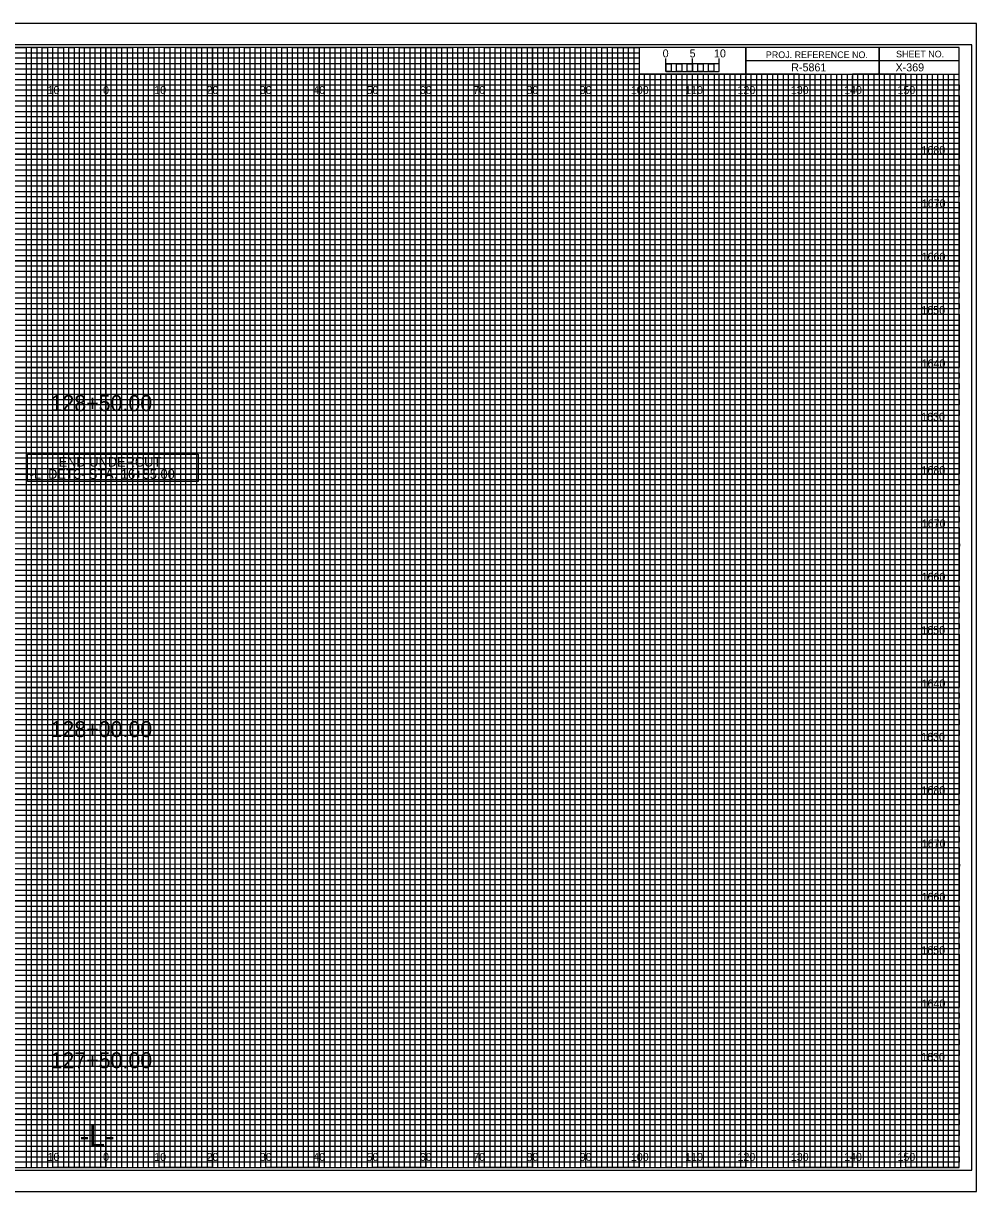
# Model space of a CAD drawing. Extents: x -13 to 323, y -5 to 2414.
# Drawn here: x 144.5 to 323.3, y 1095.5 to 1314.5 of the extents above; entities that cross this region are included whole.
import ezdxf

# ---------------------------------------------------------------- set-up
doc = ezdxf.new("R2010")
doc.units = 0
for name, color, linetype in [('Exist XS Center Line Elevation Label', 7, 'Continuous'), ('Prop Grid Mask', 7, 'Continuous'), ('Prop XS Alignment Label', 7, 'Continuous'), ('Prop XS Bar Scale Labels', 7, 'Continuous'), ('Prop XS Elevation Labels', 7, 'Continuous'), ('Prop XS Offset Labels', 7, 'Continuous'), ('Prop XS Project Number', 7, 'Continuous'), ('Prop XS Sheet Number', 7, 'Continuous'), ('Prop XS Station Labels', 7, 'Continuous'), ('Sheet Cross Section CELL', 7, 'Continuous'), ('Sheet Cross Section Grid Major CELL', 7, 'Continuous'), ('Sheet Cross Section Grid Middle CELL', 7, 'Continuous'), ('Sheet Cross Section Grid Minor 1 CELL', 7, 'Continuous'), ('Sheet Cross Section Grid Minor 2 CELL', 7, 'Continuous'), ('Sheet Cross Section Scale CELL', 7, 'Continuous'), ('Sheet Cutting Line CELL', 7, 'Continuous'), ('Sheet DOT Grid CELL', 7, 'Continuous'), ('Sheet Plot Border Inside CELL', 7, 'Continuous'), ('Sheet Plot Border Outside CELL', 7, 'Continuous')]:
    doc.layers.add(name, color=color, linetype=linetype)

msp = doc.modelspace()

# ---------------------------------------------------------------- linework, layer by layer
at = {"layer": 'Prop Grid Mask'}
msp.add_lwpolyline([(145.3, 1233.73), (177.29, 1233.73), (177.29, 1228.6), (145.3, 1228.6)], close=True, dxfattribs=at)
at = {"layer": 'Sheet Cross Section CELL'}
for p, q in [((305, 1310), (305, 1305)), ((305, 1305), (305, 1310)), ((280, 1307.5), (280, 1305)), ((320, 1307.49), (280, 1307.49)), ((280, 1305), (320, 1305))]:
    msp.add_line(p, q, dxfattribs=at)
for points in [[(320, 1310), (0, 1310), (0, 1100), (320, 1100)], [(280, 1310), (260, 1310), (260, 1305.03), (280, 1305.03)], [(320, 1310), (280, 1310), (280, 1305), (320, 1305)]]:
    msp.add_lwpolyline(points, close=True, dxfattribs=at)
at = {"layer": 'Sheet Cross Section Grid Major CELL'}
for p, q in [((150, 1310), (140, 1310)), ((150, 1100), (150, 1310)), ((170, 1310), (160, 1310)), ((160, 1310), (160, 1100)), ((170, 1100), (170, 1310)), ((190, 1310), (180, 1310)), ((180, 1310), (180, 1100)), ((190, 1100), (190, 1310)), ((210, 1310), (200, 1310)), ((200, 1310), (200, 1100)), ((210, 1100), (210, 1310)), ((230, 1310), (220, 1310)), ((220, 1310), (220, 1100)), ((230, 1100), (230, 1310)), ((250, 1310), (240, 1310)), ((240, 1310), (240, 1100)), ((250, 1100), (250, 1310)), ((260, 1310), (260, 1100)), ((270, 1100), (270, 1305)), ((290, 1305), (280, 1305)), ((280, 1305), (280, 1100)), ((290, 1100), (290, 1305)), ((310, 1305), (300, 1305)), ((300, 1305), (300, 1100)), ((310, 1100), (310, 1305)), ((160, 1100), (150, 1100)), ((180, 1100), (170, 1100)), ((200, 1100), (190, 1100)), ((220, 1100), (210, 1100)), ((240, 1100), (230, 1100)), ((260, 1100), (250, 1100)), ((280, 1100), (270, 1100)), ((300, 1100), (290, 1100)), ((320, 1100), (310, 1100)), ((320, 1100), (320, 1100))]:
    msp.add_line(p, q, dxfattribs=at)
for points in [[(0, 1300), (320, 1300), (320, 1290), (0, 1290)], [(0, 1280), (320, 1280), (320, 1270), (0, 1270)], [(0, 1260), (320, 1260), (320, 1250), (0, 1250)], [(0, 1240), (320, 1240), (320, 1230), (0, 1230)], [(0, 1220), (320, 1220), (320, 1210), (0, 1210)], [(0, 1200), (320, 1200), (320, 1190), (0, 1190)], [(0, 1180), (320, 1180), (320, 1170), (0, 1170)], [(0, 1160), (320, 1160), (320, 1150), (0, 1150)], [(0, 1140), (320, 1140), (320, 1130), (0, 1130)], [(0, 1120), (320, 1120), (320, 1110), (0, 1110)]]:
    msp.add_lwpolyline(points, dxfattribs=at)
at = {"layer": 'Sheet Cross Section Grid Middle CELL'}
for points in [[(135, 1310), (145, 1310), (145, 1100), (155, 1100), (155, 1310), (165, 1310), (165, 1100), (175, 1100), (175, 1310), (185, 1310), (185, 1100), (195, 1100), (195, 1310), (205, 1310), (205, 1100), (215, 1100), (215, 1310), (225, 1310), (225, 1100), (235, 1100), (235, 1310), (245, 1310), (245, 1100), (255, 1100), (255, 1310), (259.93, 1310), (260, 1310), (260, 1305), (264.99, 1305), (264.99, 1100), (275, 1100), (275, 1305), (285, 1305), (285, 1100), (295, 1100), (295, 1305), (305, 1305), (305, 1100), (315, 1100), (315, 1305)], [(0, 1305), (275, 1305)], [(0, 1285), (320, 1285), (320, 1295), (0, 1295)], [(0, 1265), (320, 1265), (320, 1275), (0, 1275)], [(0, 1245), (320, 1245), (320, 1255), (0, 1255)], [(0, 1225), (320, 1225), (320, 1235), (0, 1235)], [(0, 1205), (320, 1205), (320, 1215), (0, 1215)], [(0, 1185), (320, 1185), (320, 1195), (0, 1195)], [(0, 1165), (320, 1165), (320, 1175), (0, 1175)], [(0, 1145), (320, 1145), (320, 1155), (0, 1155)], [(0, 1125), (320, 1125), (320, 1135), (0, 1135)], [(0, 1105), (320, 1105), (320, 1115), (0, 1115)]]:
    msp.add_lwpolyline(points, dxfattribs=at)
at = {"layer": 'Sheet Cross Section Grid Minor 1 CELL'}
for p, q in [((0, 1309), (260, 1309)), ((260, 1307.98), (0, 1307.98)), ((260, 1309), (260, 1307.98)), ((0, 1307), (260, 1307)), ((260, 1305.89), (0, 1305.89)), ((260, 1307), (260, 1305.89)), ((0, 1304), (320, 1304))]:
    msp.add_line(p, q, dxfattribs=at)
for points in [[(0, 1303), (270, 1303), (320, 1303), (320, 1302), (0, 1302)], [(0, 1301), (320, 1301), (320, 1299), (0, 1299)], [(0, 1298), (320, 1298), (320, 1297), (0, 1296.98)], [(0, 1296), (320, 1296), (320, 1294), (0, 1294)], [(0, 1293), (320, 1293), (320, 1292), (0, 1292)], [(0, 1291), (320, 1291), (320, 1289), (0, 1289)], [(0, 1288), (320, 1288), (320, 1287), (0, 1287)], [(0, 1286), (320, 1286), (320, 1284), (0, 1284)], [(0, 1283), (320, 1283), (320, 1282), (0, 1282)], [(0, 1281), (320, 1281), (320, 1279), (0, 1279)], [(0, 1278), (320, 1278), (320, 1277), (0, 1277)], [(0, 1276), (320, 1276), (320, 1273.95), (320, 1273), (320, 1272), (0, 1272)], [(0, 1274), (320, 1274), (320, 1273), (0, 1273)], [(0, 1271), (320, 1271), (320, 1269), (0, 1269.03)], [(0, 1269.03), (320, 1269), (320, 1268), (0, 1268)], [(0, 1267), (320, 1267), (320, 1266), (0, 1266)], [(0, 1264), (320, 1264), (320, 1263), (0, 1263)], [(0, 1262), (320, 1262), (320, 1261), (0, 1261)], [(-0.07, 1258.89), (320, 1258.89), (320, 1257.88), (-0.07, 1257.88)], [(0, 1257), (320, 1257), (320, 1256), (0, 1256)], [(0, 1254), (320, 1254), (320, 1253), (0, 1253)], [(0, 1252), (320, 1252), (320, 1251), (0, 1251)], [(0, 1249), (320, 1249), (320, 1248), (0, 1248)], [(0, 1247), (320, 1247), (320, 1246), (0, 1246)], [(0, 1244), (320, 1244), (320, 1243), (0, 1243)], [(0, 1242), (320, 1242), (320, 1241), (0, 1241)], [(0, 1239), (320, 1239), (319.99, 1237.98), (0, 1238)], [(0, 1237), (320, 1237), (320, 1236), (0, 1236)], [(0, 1234), (320, 1234), (320, 1233), (0, 1233)], [(0, 1232), (320, 1232), (320, 1231), (0, 1231)], [(0, 1229), (320, 1229), (320, 1228), (0, 1228)], [(0, 1227), (320, 1227), (320, 1226), (0, 1226)], [(0, 1224), (320, 1224), (320, 1223), (0, 1223)], [(0, 1222), (320, 1222), (320, 1221), (0, 1221)], [(0, 1219), (320, 1219), (320, 1218), (0, 1218)], [(0, 1216.99), (320.07, 1216.91), (320, 1216), (0, 1216)], [(0, 1214), (320, 1214), (320, 1213), (0, 1213)], [(0, 1212), (320, 1212), (320, 1211), (0, 1211)], [(0, 1209), (320, 1209), (320, 1208), (0, 1208)], [(0, 1207), (320, 1207), (320, 1206), (0, 1206)], [(0, 1204), (320, 1204), (320, 1203), (0, 1203)], [(0, 1202), (320, 1202), (320, 1201), (0, 1201)], [(0, 1199), (320, 1199), (320, 1198), (0, 1198)], [(0, 1197), (320, 1197), (320, 1196), (0, 1196)], [(0, 1194), (320, 1194), (320, 1193), (0, 1193)], [(0, 1192), (320, 1192), (320, 1191), (0, 1191)], [(0, 1189), (320, 1189), (320, 1188), (0, 1188)], [(0, 1187), (320, 1187), (320, 1186), (0, 1186)], [(0, 1184), (320, 1184), (320, 1183), (0, 1183)], [(0, 1182), (320, 1182), (320, 1181), (0, 1181)], [(0, 1179), (320, 1179), (319.99, 1177.98), (0, 1178)], [(0, 1177), (320, 1177), (320, 1176), (0, 1176)], [(0, 1174), (320, 1174), (320, 1173), (0, 1173)], [(0, 1172), (320, 1172), (320, 1171), (0, 1171)], [(0, 1169), (320, 1169), (320, 1168), (0, 1168)], [(0, 1167), (320, 1167), (320, 1166), (0, 1166)], [(0, 1164), (320, 1164), (320, 1163), (0, 1163)], [(0, 1162), (320, 1162), (320, 1161), (0, 1161)], [(0, 1159), (320, 1159), (320, 1158), (0, 1158)], [(0, 1156.99), (320.07, 1156.91), (320, 1156), (0, 1156)], [(0, 1154), (320, 1154), (320, 1153), (0, 1153)], [(0, 1152), (320, 1152), (320, 1151), (0, 1151)], [(0, 1149), (320, 1149), (320, 1148), (0, 1148)], [(0, 1147), (320, 1147), (320, 1146), (0, 1146)], [(0, 1144), (320, 1144), (320, 1143), (0, 1143)], [(0, 1142), (320, 1142), (320, 1141), (0, 1141)], [(0, 1139), (320, 1139), (320, 1138), (0, 1138)], [(0, 1137), (320, 1137), (320, 1136), (0, 1136)], [(0, 1134), (320, 1134), (320, 1133), (0, 1133)], [(0, 1132), (320, 1132), (320, 1131), (0, 1131)], [(0, 1129), (320, 1129), (320, 1128), (0, 1128)], [(0, 1127), (320, 1127), (320, 1126), (0, 1126)], [(0, 1124), (320, 1124), (320, 1123), (0, 1123)], [(0, 1122), (320, 1122), (320, 1121), (0, 1121)], [(0, 1119), (320, 1119), (320, 1118), (0, 1118)], [(0, 1117), (320, 1117), (320, 1116), (0, 1116)], [(0, 1114), (320, 1114), (320, 1113), (0, 1113)], [(0, 1112), (320, 1112), (320, 1111), (0, 1111)], [(0, 1109), (320, 1109), (320, 1108), (0, 1108)], [(0, 1107), (320, 1107), (320, 1106), (0, 1106)], [(0, 1104), (320, 1104), (320, 1103), (0, 1103)], [(0, 1102), (320, 1102), (320, 1101), (0, 1101)]]:
    msp.add_lwpolyline(points, dxfattribs=at)
at = {"layer": 'Sheet Cross Section Grid Minor 2 CELL'}
for p, q in [((267, 1305), (266.01, 1305)), ((266.01, 1305), (266.01, 1100)), ((267, 1100), (267, 1305)), ((269, 1305), (268, 1305)), ((268, 1305), (268, 1100)), ((269, 1100), (269, 1305)), ((266.01, 1100), (265, 1100)), ((268, 1100), (267, 1100))]:
    msp.add_line(p, q, dxfattribs=at)
for points in [[(145, 1100), (146, 1100), (146, 1310), (147, 1310), (147, 1100)], [(147, 1100), (148, 1100), (148, 1310), (149, 1310), (149, 1100)], [(150, 1100), (151, 1100), (151, 1310), (152, 1310), (152, 1100)], [(152, 1100), (153, 1100), (153, 1310), (154, 1310), (154, 1100)], [(155, 1100), (156, 1100), (156, 1310), (157, 1310), (157, 1100)], [(157, 1100), (158, 1100), (158, 1310), (159, 1310), (159, 1100)], [(160, 1100), (161, 1100), (161, 1310), (162, 1310), (162, 1100)], [(162, 1100), (163, 1100), (163, 1310), (164, 1310), (164, 1100)], [(165, 1100), (166, 1100), (166, 1310), (167, 1310), (167, 1100)], [(167, 1100), (168, 1100), (168, 1310), (169, 1310), (169, 1100)], [(170, 1100), (171, 1100), (171, 1310), (172, 1310), (172, 1100)], [(172, 1100), (173, 1100), (173, 1310), (174, 1310), (174, 1100)], [(175, 1100), (176, 1100), (176, 1310), (177, 1310), (177, 1100)], [(177, 1100), (178, 1100), (178, 1310), (179, 1310), (179, 1100)], [(180, 1100), (181, 1100), (181, 1310), (182, 1310), (182, 1100)], [(182, 1100), (183, 1100), (183, 1310), (184, 1310), (184, 1100)], [(185, 1100), (186, 1100), (186, 1310), (187, 1310), (187, 1100)], [(187, 1100), (188, 1100), (188, 1310), (189, 1310), (189, 1100)], [(190, 1100), (191, 1100), (191, 1310), (192, 1310), (192, 1100)], [(192, 1100), (193, 1100), (193, 1310), (194, 1310), (194, 1100)], [(195, 1100), (196, 1100), (196, 1310), (197, 1310), (197, 1100)], [(197, 1100), (198, 1100), (198, 1310), (199, 1310), (199, 1100)], [(200, 1100), (201, 1100), (201, 1310), (202, 1310), (202, 1100)], [(202, 1100), (203, 1100), (203, 1310), (204, 1310), (204, 1100)], [(205, 1100), (206, 1100), (206, 1310), (207, 1310), (207, 1100)], [(207, 1100), (208, 1100), (208, 1310), (209, 1310), (209, 1100)], [(210, 1100), (211, 1100), (211, 1310), (212, 1310), (212, 1100)], [(212, 1100), (213, 1100), (213, 1310), (214, 1310), (214, 1100)], [(215, 1100), (216, 1100), (216, 1310), (217, 1310), (217, 1100)], [(217, 1100), (218, 1100), (218, 1310), (219, 1310), (219, 1100)], [(220, 1100), (221, 1100), (221, 1310), (222, 1310), (222, 1100)], [(222, 1100), (223, 1100), (223, 1310), (224, 1310), (224, 1100)], [(225, 1100), (226, 1100), (226, 1310), (227, 1310), (227, 1100)], [(227, 1100), (228, 1100), (228, 1310), (229, 1310), (229, 1100)], [(230, 1100), (231, 1100), (231, 1310), (232, 1310), (232, 1100)], [(232, 1100), (233, 1100), (233, 1310), (234, 1310), (234, 1100)], [(235, 1100), (236, 1100), (236, 1310), (237, 1310), (237, 1100)], [(237, 1100), (238, 1100), (238, 1310), (239, 1310), (239, 1100)], [(240, 1100), (241, 1100), (241, 1310), (242, 1310), (242, 1100)], [(242, 1100), (243, 1100), (243, 1310), (244, 1310), (244, 1100)], [(245, 1100), (246, 1100), (246, 1310), (247, 1310), (247, 1100)], [(247, 1100), (248, 1100), (248, 1310), (249, 1310), (249, 1100)], [(250, 1100), (251, 1100), (251, 1310), (252, 1310), (252, 1100)], [(252, 1100), (253, 1100), (253, 1310), (254, 1310), (254, 1100)], [(255, 1100), (256, 1100), (256, 1310), (257, 1310), (257, 1100)], [(257, 1100), (258, 1100), (258, 1310), (259, 1310), (259, 1100)], [(260, 1100), (261, 1100), (261, 1305), (262.02, 1305), (262.02, 1100)], [(262, 1100), (263, 1100), (263, 1305), (263.99, 1305), (263.99, 1100)], [(270, 1100), (270.98, 1100), (270.98, 1305), (272, 1305), (272, 1100)], [(272, 1100), (273, 1100), (273, 1305), (274.05, 1305), (274.05, 1100)], [(275, 1100), (276, 1100), (276, 1305), (277, 1305), (277, 1100)], [(277, 1100), (278, 1100), (278, 1305), (279, 1305), (279, 1100)], [(280, 1100), (281, 1100), (281, 1305), (282, 1305), (282, 1100)], [(282, 1100), (283, 1100), (283, 1305), (284, 1305), (284, 1100)], [(285, 1100), (286, 1100), (286, 1305), (287, 1305), (287, 1100)], [(287, 1100), (288, 1100), (288, 1305), (289, 1305), (289, 1100)], [(290, 1100), (291, 1100), (291, 1305), (292, 1305), (292, 1100)], [(292, 1100), (293, 1100), (293, 1305), (294, 1305), (294, 1100)], [(295, 1100), (296, 1100), (296, 1305), (297, 1305), (297, 1100)], [(297, 1100), (298, 1100), (298, 1305), (299, 1305), (299, 1100)], [(300, 1100), (301, 1100), (301, 1305), (302, 1305), (302, 1100)], [(302, 1100), (303, 1100), (303, 1305), (304, 1305), (304, 1100)], [(305, 1100), (306, 1100), (306, 1305), (307, 1305), (307, 1100)], [(307, 1100), (308, 1100), (308, 1305), (309, 1305), (309, 1100)], [(310, 1100), (311, 1100), (311, 1305), (312, 1305), (312, 1100)], [(312, 1100), (313, 1100), (313, 1305), (314, 1305), (314, 1100)], [(315, 1100), (316, 1100), (316, 1305), (317, 1305), (317, 1100)], [(317, 1100), (318, 1100), (318, 1305), (319, 1305), (319, 1100)]]:
    msp.add_lwpolyline(points, dxfattribs=at)
at = {"layer": 'Sheet Cross Section Scale CELL'}
for p, q in [((265, 1305.49), (265, 1307.9)), ((265, 1306.9), (265, 1307.9)), ((270, 1305.49), (270, 1307.9)), ((275, 1305.49), (275, 1307.9)), ((275, 1306.9), (275, 1307.9))]:
    msp.add_line(p, q, dxfattribs=at)
for points in [[(275, 1306.9), (265, 1306.9), (265, 1305.49), (275, 1305.49)], [(265, 1306.9), (266, 1306.9), (266, 1305.49), (265, 1305.49)], [(267, 1306.9), (268, 1306.9), (268, 1305.49), (267, 1305.49)], [(269, 1306.9), (270, 1306.9), (270, 1305.49), (269, 1305.49)], [(271, 1306.9), (272, 1306.9), (272, 1305.49), (271, 1305.49)], [(273, 1306.9), (274, 1306.9), (274, 1305.49), (273, 1305.49)]]:
    msp.add_lwpolyline(points, close=True, dxfattribs=at)
at = {"layer": 'Sheet Cutting Line CELL'}
for p, q in [((323.3, 1314.5), (-13.4, 1314.5)), ((-13.4, 1095.5), (323.3, 1095.5))]:
    msp.add_line(p, q, dxfattribs=at)
at = {"layer": 'Sheet DOT Grid CELL'}
for p, q in [((150, 1100), (150, 1310)), ((160, 1100), (160, 1310)), ((170, 1100), (170, 1310)), ((180, 1100), (180, 1310)), ((190, 1100), (190, 1310)), ((200, 1100), (200, 1310)), ((210, 1100), (210, 1310)), ((220, 1100), (220, 1310)), ((230, 1100), (230, 1310)), ((240, 1100), (240, 1310)), ((250, 1100), (250, 1310)), ((260, 1100), (260, 1304.69)), ((270, 1100), (270, 1304.69)), ((280, 1100), (280, 1304.69)), ((290, 1100), (290, 1304.69)), ((300, 1100), (300, 1304.69)), ((310, 1100), (310, 1304.69)), ((0, 1300), (320, 1300)), ((0, 1290), (320, 1290)), ((0, 1280), (320, 1280)), ((0, 1270), (320, 1270)), ((0, 1260), (320, 1260)), ((0, 1250), (320, 1250)), ((0, 1240), (320, 1240)), ((0, 1230), (320, 1230)), ((0, 1220), (320, 1220)), ((0, 1210), (320, 1210)), ((0, 1200), (320, 1200)), ((0, 1190), (320, 1190)), ((0, 1180), (320, 1180)), ((0, 1170), (320, 1170)), ((0, 1160), (320, 1160)), ((0, 1150), (320, 1150)), ((0, 1140), (320, 1140)), ((0, 1130), (320, 1130)), ((0, 1120), (320, 1120)), ((0, 1110), (320, 1110))]:
    msp.add_line(p, q, dxfattribs=at)
at = {"layer": 'Sheet Plot Border Inside CELL'}
msp.add_lwpolyline([(-10.8, 1099.5), (322.4, 1099.5), (322.4, 1310.5), (-10.8, 1310.5)], close=True, dxfattribs=at)
at = {"layer": 'Sheet Plot Border Outside CELL'}
msp.add_lwpolyline([(-13.4, 1095.5), (323.3, 1095.5), (323.3, 1314.5), (-13.4, 1314.5)], close=True, dxfattribs=at)

# ---------------------------------------------------------------- texts
at = {"layer": 'Exist XS Center Line Elevation Label'}
for s, p in [('END UNDERCUT ', (151.11, 1231.41)), ('-L_DET3- STA. 16+55.00', (145.67, 1229.12))]:
    msp.add_text(s, height=1.8, dxfattribs=at).set_placement(p)
at = {"layer": 'Prop XS Alignment Label'}
msp.add_text('-L-', height=4, dxfattribs=at).set_placement((155.06, 1104))
at = {"layer": 'Prop XS Bar Scale Labels'}
for s, p in [('5', (269.47, 1308.12)), ('10', (274.04, 1308.12))]:
    msp.add_text(s, height=1.5, dxfattribs=at).set_placement(p)
at = {"layer": 'Prop XS Elevation Labels'}
for s, p in [('1680', (312.95, 1290)), ('1670', (313, 1280)), ('1660', (312.97, 1270)), ('1650', (312.92, 1260)), ('1640', (312.97, 1250)), ('1630', (312.89, 1240)), ('1680', (312.95, 1230)), ('1670', (313, 1220)), ('1660', (312.97, 1210)), ('1650', (312.92, 1200)), ('1640', (312.97, 1190)), ('1630', (312.89, 1180)), ('1680', (312.95, 1170)), ('1670', (313, 1160)), ('1660', (312.97, 1150)), ('1650', (312.92, 1140)), ('1640', (312.97, 1130)), ('1630', (312.89, 1120))]:
    msp.add_text(s, height=1.5, dxfattribs=at).set_placement(p)
at = {"layer": 'Prop XS Offset Labels'}
for s, p in [('10', (149.04, 1301.25)), ('0', (159.45, 1301.25)), ('0', (159.45, 1301.25)), ('10', (169.04, 1301.25)), ('20', (178.86, 1301.25)), ('30', (188.86, 1301.25)), ('40', (198.86, 1301.25)), ('50', (208.86, 1301.25)), ('60', (218.86, 1301.25)), ('70', (228.86, 1301.25)), ('80', (238.86, 1301.25)), ('90', (248.86, 1301.25)), ('100', (258.44, 1301.25)), ('110', (268.62, 1301.25)), ('120', (278.44, 1301.25)), ('130', (288.44, 1301.25)), ('140', (298.44, 1301.25)), ('150', (308.44, 1301.25)), ('10', (149.04, 1101.25)), ('0', (159.45, 1101.25)), ('0', (159.45, 1101.25)), ('10', (169.04, 1101.25)), ('20', (178.86, 1101.25)), ('30', (188.86, 1101.25)), ('40', (198.86, 1101.25)), ('50', (208.86, 1101.25)), ('60', (218.86, 1101.25)), ('70', (228.86, 1101.25)), ('80', (238.86, 1101.25)), ('90', (248.86, 1101.25)), ('100', (258.44, 1101.25)), ('110', (268.62, 1101.25)), ('120', (278.44, 1101.25)), ('130', (288.44, 1101.25)), ('140', (298.44, 1101.25)), ('150', (308.44, 1101.25))]:
    msp.add_text(s, height=1.5, dxfattribs=at).set_placement(p)
at = {"layer": 'Prop XS Project Number'}
msp.add_text('R-5861', height=1.5, dxfattribs=at).set_placement((288.53, 1305.5))
at = {"layer": 'Prop XS Sheet Number'}
msp.add_text('X-369', height=1.5, dxfattribs=at).set_placement((308.09, 1305.5))
at = {"layer": 'Prop XS Station Labels'}
for s, p in [('128+50.00', (149.59, 1241.82)), ('128+00.00', (149.59, 1180.7)), ('127+50.00', (149.59, 1118.63))]:
    msp.add_text(s, height=3, dxfattribs=at).set_placement(p)
at = {"layer": 'Sheet Cross Section CELL'}
for s, p in [('PROJ. REFERENCE NO.', (283.77, 1307.99)), ('SHEET NO.', (308.19, 1308.12))]:
    msp.add_text(s, height=1.25, dxfattribs=at).set_placement(p)
at = {"layer": 'Sheet Cross Section Scale CELL'}
msp.add_text('0', height=1.5, dxfattribs=at).set_placement((264.41, 1308.12))

doc.saveas('drawing.dxf')
